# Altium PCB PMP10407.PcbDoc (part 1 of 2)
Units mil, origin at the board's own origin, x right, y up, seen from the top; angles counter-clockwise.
Board outline 4400 x 1900 mil, 4 copper layers (Top Layer, Signal Layer 1, Signal Layer 2, Bottom Layer), stack 60.6 mil thick; 66 components, 38 nets, 182 pads, 41 vias.
Unrouted connection lines stored in the file: 1.
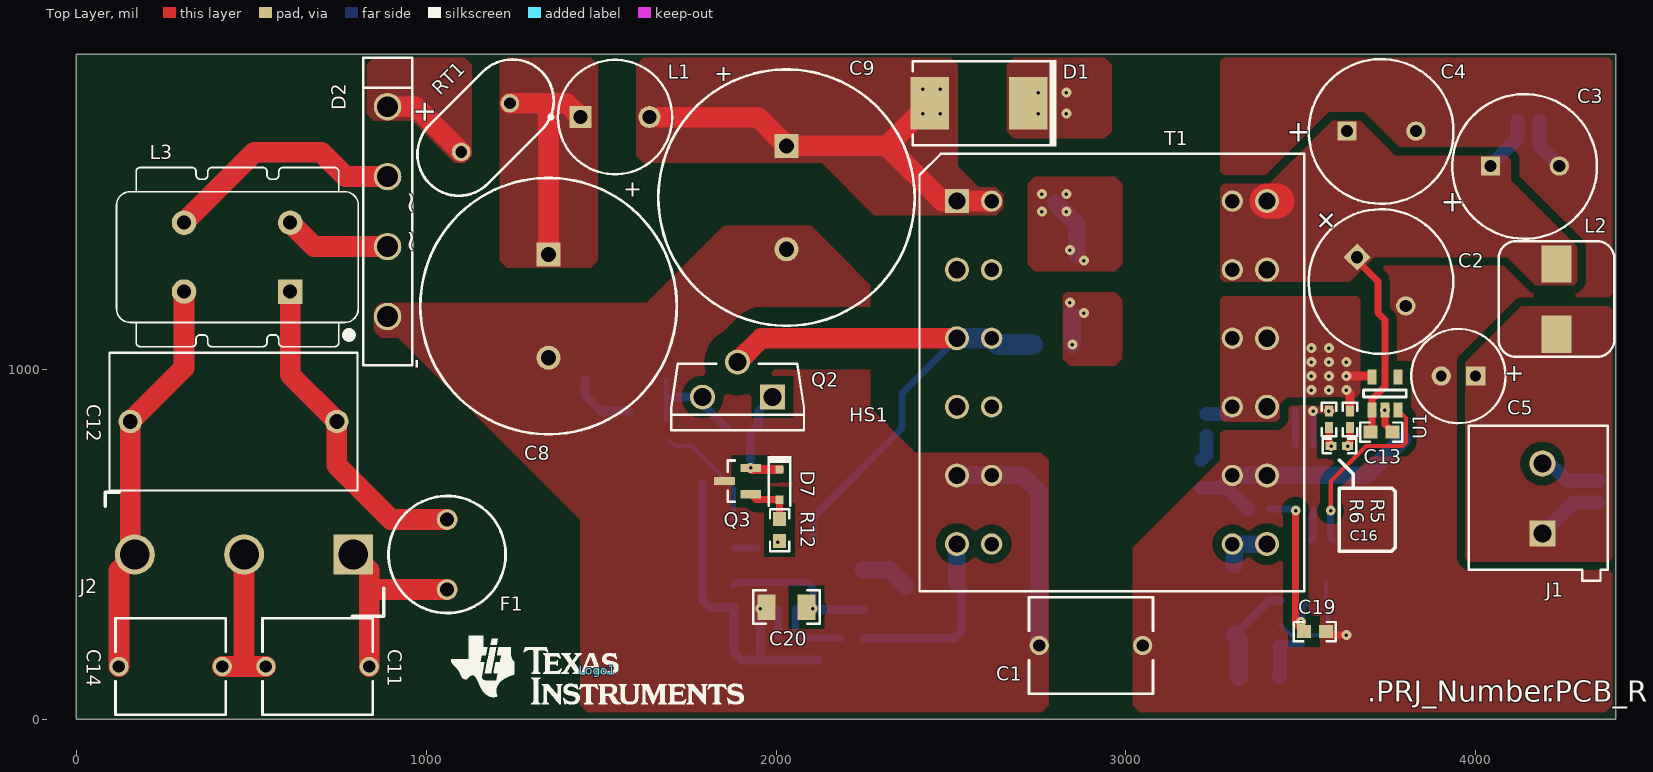
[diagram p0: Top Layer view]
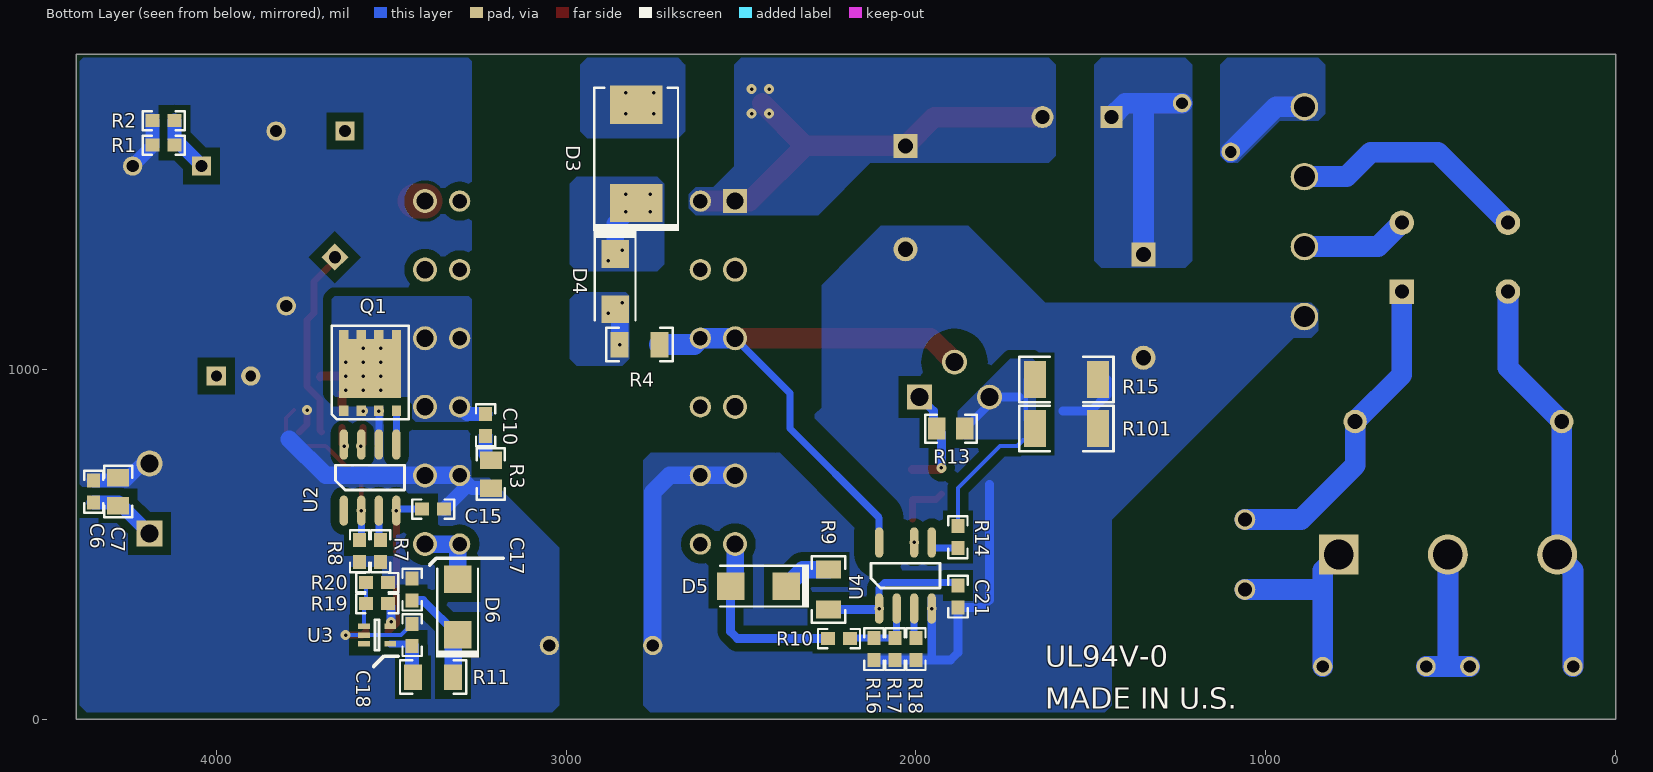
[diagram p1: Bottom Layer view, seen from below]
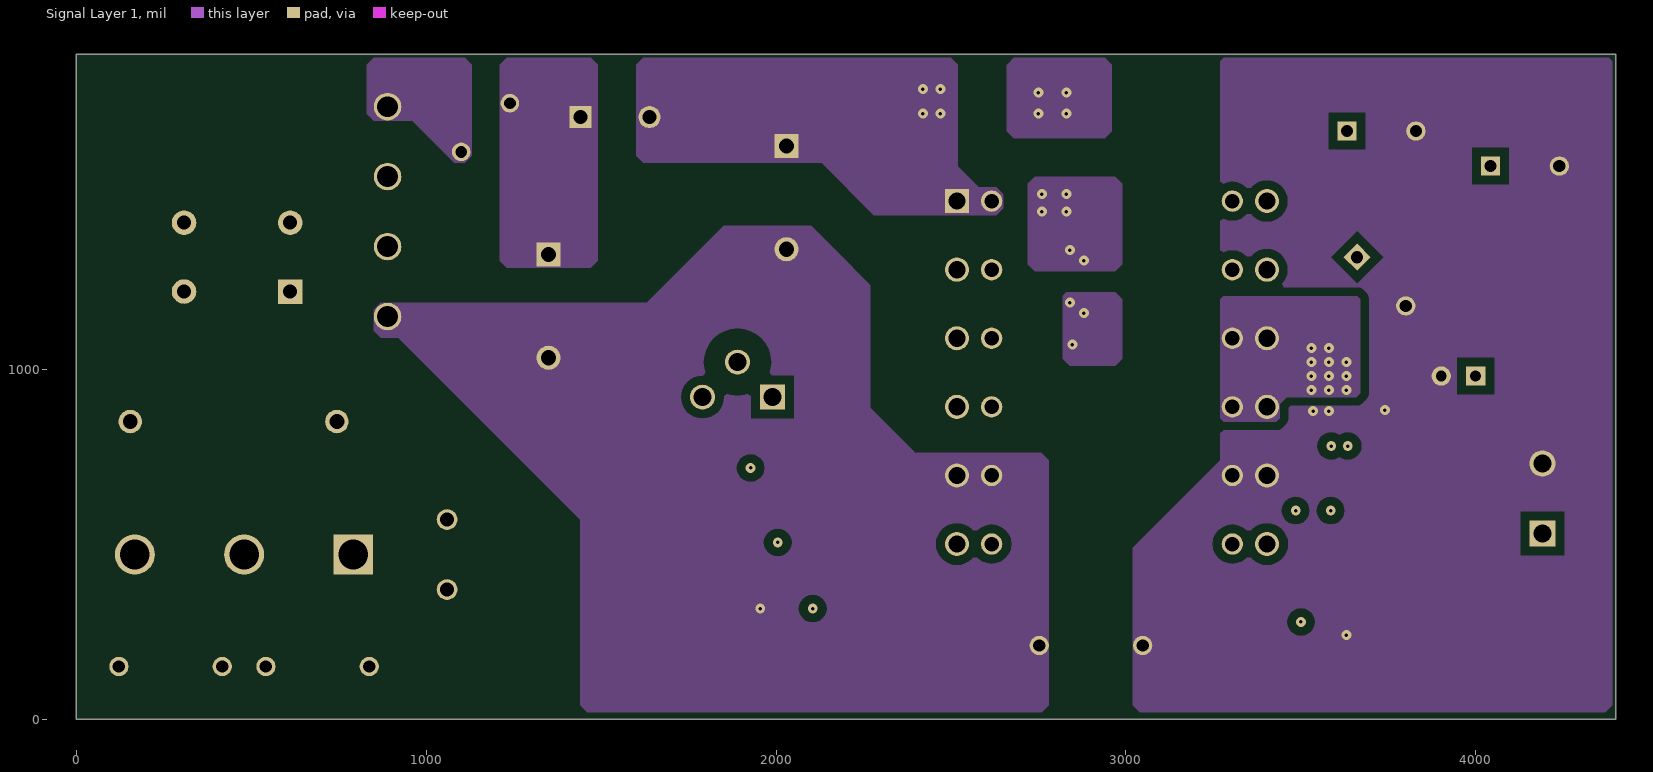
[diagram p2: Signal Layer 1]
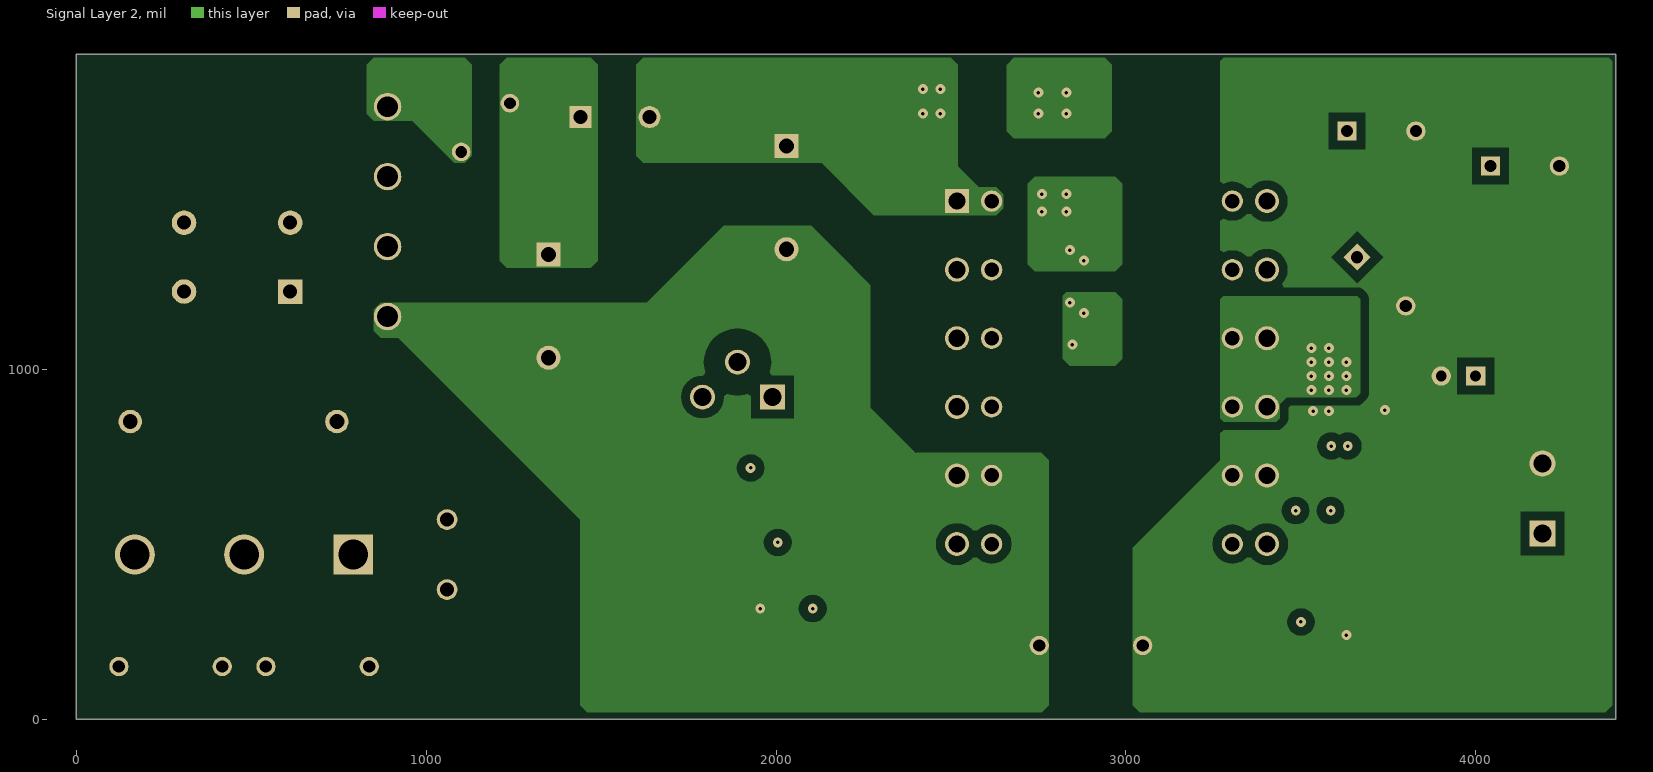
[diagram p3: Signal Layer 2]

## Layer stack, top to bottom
Top Solder: solder mask 0.4, Solder Resist, Dk 3.5
Top Layer: signal copper 1.4
Dielectric1: core 10, FR-4, Dk 4.8
Signal Layer 1: signal copper 1.4
Dielectric 3: prepreg 35, FR-4, Dk 4.2
Signal Layer 2: signal copper 1.4
Dielectric 2: core 10, FR-4, Dk 4.2
Bottom Layer: signal copper 1.4
Bottom Solder: solder mask 0.4, Solder Resist, Dk 3.5

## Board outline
0,0 4400,0 4400,1900 0,1900

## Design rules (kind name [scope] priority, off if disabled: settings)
AcuteAngle [All] p1: minimum=4.50000000000000E+0001 checktracksonly=FALSE
AssemblyTestPointUsage [All] p1: valid=2
Clearance Clearance_1 [InNetClass('HV_Pri') vs InNet('GND')] p1: gap=60
Clearance Clearance_BoardEdge_MountingHoles [OnCopper and InComponentClass('Mounting Holes') vs IsKeepOut] p2: gap=40
Clearance Clearance_BoardEdge_Poly [OnCopper and InPoly vs IsKeepOut] p3: gap=25
Clearance Clearance_BoardEdge [OnCopper and Not InComponentClass('Logo') and not InComponentClass('FiducialMark') and not InRegion(1000,500,4000,800) and Not IsKeepout vs IsKeepOut] p4: gap=75
Clearance Clearance_Poly [InPolygon] p5: gap=25
Clearance [All] p6: gap=9.5
ComponentClearance ComponentClearance_Logo [InComponentClass(Logo)] p1: gap=50 collisioncheckmode=3 verticalgap=10 showdistances=FALSE
ComponentClearance ComponentClearance_ScrewToNut [(HasFootprint('NY PMS 440 0025 PH')) vs (HasFootprint('Keystone_1902C'))] p2: gap=5 collisioncheckmode=3 verticalgap=10 showdistances=FALSE
ComponentClearance ComponentClearance_MountingHoles [InComponentClass('Mounting Holes')] p3: gap=10 collisioncheckmode=3 verticalgap=100000 showdistances=FALSE
ComponentClearance ComponentClearance_SmallPassives [HasFootprint('0201*') or HasFootprint('0402*') or HasFootprint('0508') or HasFootprint('0603*') or HasFootprint('0612') or HasFootprint('0805*') or HasFootprint('0815*') or HasFootprint('0830*') or HasFootprint('1206*') or HasFootprint('1210*') or HasFootprint('1808*') or HasFootprint('1812*') or HasFootprint('1825*') or HasFootprint('2010*') or HasFootprint('2220*') or HasFootprint('2225*') or HasFootprint('2512*') or HasFootprint('2728*') or HasFootprint('3518*') vs HasFootprint('0201*') or HasFootprint('0402*') or HasFootprint('0508') or HasFootprint('0603*') or HasFootprint('0612') or HasFootprint('0805*') or HasFootprint('0815*') or HasFootprint('0830*') or HasFootprint('1206*') or HasFootprint('1210*') or HasFootprint('1808*') or HasFootprint('1812*') or HasFootprint('1825*') or HasFootprint('2010*') or HasFootprint('2220*') or HasFootprint('2225*') or HasFootprint('2512*') or HasFootprint('2728*') or HasFootprint('3518*')] p4: gap=20 collisioncheckmode=3 verticalgap=9.5 showdistances=FALSE
ComponentClearance ComponentClearance_THtoSMT [IsThruComponent vs IsSMTComponent] p5: gap=9.5 collisioncheckmode=3 verticalgap=9.5 showdistances=FALSE
ComponentClearance ComponentClearance_THtoTH [IsThruComponent vs IsThruComponent] p6: gap=9.5 collisioncheckmode=3 verticalgap=9.5 showdistances=FALSE
ComponentClearance [All] p7: gap=9.5 collisioncheckmode=3 verticalgap=9.5 showdistances=FALSE
DiffPairsRouting [All] p1: maxlimit=100 minlimit=10 mostfreqgap=10 toplayer_minwidth=15 toplayer_maxwidth=15 toplayer_prefwidth=15 midlayer1_minwidth=15 midlayer1_maxwidth=15 midlayer1_prefwidth=15 midlayer2_minwidth=15 midlayer2_maxwidth=15 midlayer2_prefwidth=15 bottomlayer_minwidth=15 bottomlayer_maxwidth=15 bottomlayer_prefwidth=15 maxuncoupledlength=1000
FabricationTestPointUsage TestPointUsage [All] p1: valid=2 allowmultiple=FALSE
FabricationTestpoint Testpoint [All] p1: side=3 testpointundercomponent=TRUE minsize=40 maxsize=100 preferedsize=60 minholesize=0 maxholesize=40 preferedholesize=32 testpointgrid=1 allowsidetop=TRUE allowsidebottom=TRUE usegrid=TRUE gridtolerance=0.01
FanoutControl Fanout_LCC [IsLCC] p1: bgadir=Out bgaviamode=Centered fanoutstyle=Auto fanoutdirection=Alternating viagrid=1 // Fanout_LCC (Default Rule)
FanoutControl Fanout_BGA [IsBGA] p2: bgadir=Out bgaviamode=Centered fanoutstyle=Auto fanoutdirection=Alternating viagrid=1 // Fanout_BGA (Default Rule)
FanoutControl Fanout_Default [All] p4: bgadir=Out bgaviamode=Centered fanoutstyle=Auto fanoutdirection=Alternating viagrid=1 // Fanout_Default (Default Rule)
FanoutControl Fanout_Small [(CompPinCount < 5)] p5: bgadir=Out bgaviamode=Centered fanoutstyle=Auto fanoutdirection=OutThenIn viagrid=1 // Fanout_Small (Default Rule)
Height [All] p1: minheight=0 maxheight=8000 prefheight=3000
HoleSize [All] p1: absolutevalues=TRUE maxlimit=251 minlimit=8 maxpercent=80.000 minpercent=20.000
HoleToHoleClearance [All] p1: gap=8 allowstackedmicrovias=TRUE
MinimumAnnularRing [All] p1: minimumring=6
MinimumSolderMaskSliver MinimumSolderMaskSliver_Logo [InComponentClass('Logo') vs InComponentClass('Logo')] p1: minsoldermaskwidth=0.7
MinimumSolderMaskSliver [All] p2: minsoldermaskwidth=3.5
PlaneConnect [All] p1: planeconnectstyle=Relief reliefexpansion=10 reliefentries=4 reliefconductorwidth=10 reliefairgap=10
PolygonConnect PolygonConnect_14 [All vs IsNamedPolygon('NetC2_1') Or  IsNamedPolygon('D2_1') Or  IsNamedPolygon('D3_1') Or  IsNamedPolygon('D1_1') Or  IsNamedPolygon('C8_1') Or  IsNamedPolygon('C10_2') Or  IsNamedPolygon('GND') Or  IsNamedPolygon('C10_2') Or  IsNamedPolygon('C9_1') Or  IsNamedPolygon('C10_2') Or  IsNamedPolygon('Q2_3') Or  IsNamedPolygon('C10_2') Or  IsNamedPolygon('GND') Or  IsNamedPolygon('D2_1') Or  IsNamedPolygon('C9_1') Or  IsNamedPolygon('D1_1') Or  IsNamedPolygon('D4_2') Or  IsNamedPolygon('C8_1')] p1: connectstyle=Direct reliefconductorwidth=10 reliefentries=4 polygonreliefangle="90 Angle" airgapwidth=10
PolygonConnect PolygonConnect_13 [All vs IsNamedPolygon('GND') Or  IsNamedPolygon('GND2') Or  IsNamedPolygon('GND') Or  IsNamedPolygon('GND2') Or  IsNamedPolygon('Q2_3') Or  IsNamedPolygon('D1_1') Or  IsNamedPolygon('D1_1') Or  IsNamedPolygon('C2_1') Or  IsNamedPolygon('C9_1') Or  IsNamedPolygon('C2_1') Or  IsNamedPolygon('C8_1') Or  IsNamedPolygon('D3_1') Or  IsNamedPolygon('C8_1') Or  IsNamedPolygon('D2_1') Or  IsNamedPolygon('C5_1') Or  IsNamedPolygon('C9_1') Or  IsNamedPolygon('D4_2') Or  IsNamedPolygon('C5_1') Or  IsNamedPolygon('C10_2') Or  IsNamedPolygon('C10_2') Or  IsNamedPolygon('D2_1')] p2: connectstyle=Direct reliefconductorwidth=10 reliefentries=4 polygonreliefangle="90 Angle" airgapwidth=10
PolygonConnect PolygonConnect_12 [All vs IsNamedPolygon('GND') Or  IsNamedPolygon('GND') Or  IsNamedPolygon('C5_1') Or  IsNamedPolygon('C8_1') Or  IsNamedPolygon('D2_1') Or  IsNamedPolygon('Q2_3') Or  IsNamedPolygon('C9_1') Or  IsNamedPolygon('C10_2') Or  IsNamedPolygon('D3_1') Or  IsNamedPolygon('C9_1') Or  IsNamedPolygon('D4_2') Or  IsNamedPolygon('C2_1') Or  IsNamedPolygon('C2_1') Or  IsNamedPolygon('C10_2') Or  IsNamedPolygon('D2_1') Or  IsNamedPolygon('D1_1') Or  IsNamedPolygon('C8_1') Or  IsNamedPolygon('D1_1') Or  IsNamedPolygon('C5_1')] p3: connectstyle=Direct reliefconductorwidth=10 reliefentries=4 polygonreliefangle="90 Angle" airgapwidth=10
PolygonConnect PolygonConnect_11 [All vs IsNamedPolygon('C10_2') Or  IsNamedPolygon('C2_1') Or  IsNamedPolygon('C5_1') Or  IsNamedPolygon('D1_1') Or  IsNamedPolygon('C9_1') Or  IsNamedPolygon('C8_1') Or  IsNamedPolygon('C9_1') Or  IsNamedPolygon('C10_2') Or  IsNamedPolygon('C2_1') Or  IsNamedPolygon('D1_1') Or  IsNamedPolygon('C8_1') Or  IsNamedPolygon('D4_2') Or  IsNamedPolygon('D2_1') Or  IsNamedPolygon('C5_1') Or  IsNamedPolygon('D3_1') Or  IsNamedPolygon('D2_1')] p4: connectstyle=Direct reliefconductorwidth=10 reliefentries=4 polygonreliefangle="90 Angle" airgapwidth=10
PolygonConnect PolygonConnect_10 [All vs IsNamedPolygon('C8_1') Or  IsNamedPolygon('C2_1') Or  IsNamedPolygon('D1_1') Or  IsNamedPolygon('D1_1') Or  IsNamedPolygon('D4_2') Or  IsNamedPolygon('D2_1') Or  IsNamedPolygon('D3_1') Or  IsNamedPolygon('C9_1') Or  IsNamedPolygon('D2_1') Or  IsNamedPolygon('C9_1') Or  IsNamedPolygon('C8_1')] p5: connectstyle=Direct reliefconductorwidth=10 reliefentries=4 polygonreliefangle="90 Angle" airgapwidth=10
PolygonConnect PolygonConnect_9 [All vs IsNamedPolygon('C4_1') Or  IsNamedPolygon('C2_1_T') Or  IsNamedPolygon('C2_1_B') Or  IsNamedPolygon('D4_1') Or  IsNamedPolygon('GND2') Or  IsNamedPolygon('GND') Or  IsNamedPolygon('D4_1') Or  IsNamedPolygon('D2_1') Or  IsNamedPolygon('Q1_3_B') Or  IsNamedPolygon('C6_1') Or  IsNamedPolygon('GND2_T') Or  IsNamedPolygon('D2_1') Or  IsNamedPolygon('GND') Or  IsNamedPolygon('GND2') Or  IsNamedPolygon('GND2')] p6: connectstyle=Direct reliefconductorwidth=10 reliefentries=4 polygonreliefangle="90 Angle" airgapwidth=10
PolygonConnect PolygonConnect_8 [All vs IsNamedPolygon('GND2') Or  IsNamedPolygon('C2_1_B') Or  IsNamedPolygon('C6_1') Or  IsNamedPolygon('GND') Or  IsNamedPolygon('D2_1') Or  IsNamedPolygon('Q1_3_B') Or  IsNamedPolygon('D4_1') Or  IsNamedPolygon('C2_1_T') Or  IsNamedPolygon('D2_1') Or  IsNamedPolygon('D4_1') Or  IsNamedPolygon('GND2_T') Or  IsNamedPolygon('GND') Or  IsNamedPolygon('C4_1')] p7: connectstyle=Direct reliefconductorwidth=10 reliefentries=4 polygonreliefangle="90 Angle" airgapwidth=10
PolygonConnect PolygonConnect_7 [All vs IsNamedPolygon('Q1_3_B') Or  IsNamedPolygon('C2_1_T') Or  IsNamedPolygon('D4_1') Or  IsNamedPolygon('C4_1') Or  IsNamedPolygon('D2_1') Or  IsNamedPolygon('GND2_T') Or  IsNamedPolygon('D2_1') Or  IsNamedPolygon('D4_1') Or  IsNamedPolygon('C2_1_B')] p8: connectstyle=Direct reliefconductorwidth=10 reliefentries=4 polygonreliefangle="90 Angle" airgapwidth=10
PolygonConnect PolygonConnect_6 [All vs IsNamedPolygon('C1_1_T') Or  IsNamedPolygon('GND_T') Or  IsNamedPolygon('C5_1_B') Or  IsNamedPolygon('D4_1_B') Or  IsNamedPolygon('D2_1_B') Or  IsNamedPolygon('D4_1_T') Or  IsNamedPolygon('C3_2_T') Or  IsNamedPolygon('GND') Or  IsNamedPolygon('C2_1_T') Or  IsNamedPolygon('Q1_3_B') Or  IsNamedPolygon('C3_2_B') Or  IsNamedPolygon('C5_1_T') Or  IsNamedPolygon('C5_1_B') Or  IsNamedPolygon('D2_1_T') Or  IsNamedPolygon('C2_1_B')] p9: connectstyle=Direct reliefconductorwidth=10 reliefentries=4 polygonreliefangle="90 Angle" airgapwidth=10
PolygonConnect PolygonConnect_5 [All vs IsNamedPolygon('C1_1_T') Or  IsNamedPolygon('D2_1_T') Or  IsNamedPolygon('C2_1_T') Or  IsNamedPolygon('D4_1_B') Or  IsNamedPolygon('D2_1_B') Or  IsNamedPolygon('D4_1_T') Or  IsNamedPolygon('Q1_3_B') Or  IsNamedPolygon('C2_1_B')] p10: connectstyle=Direct reliefconductorwidth=10 reliefentries=4 polygonreliefangle="90 Angle" airgapwidth=10
PolygonConnect PolygonConnect_4 [All vs IsNamedPolygon('D1_2_B') Or  IsNamedPolygon('D1_3_T') Or  IsNamedPolygon('D1_3_B') Or  IsNamedPolygon('C2_1_T') Or  IsNamedPolygon('C5_1_B') Or  IsNamedPolygon('C5_1_T') Or  IsNamedPolygon('C7_1_B') Or  IsNamedPolygon('C7_1_T') Or  IsNamedPolygon('D1_2_T') Or  IsNamedPolygon('VCS_T') Or  IsNamedPolygon('L4_9_T') Or  IsNamedPolygon('C12_1_T') Or  IsNamedPolygon('D4_1_T') Or  IsNamedPolygon('C9_1_T') Or  IsNamedPolygon('Q7_4_B') Or  IsNamedPolygon('R23_2_B') Or  IsNamedPolygon('VREC_T') Or  IsNamedPolygon('C9_1_B') Or  IsNamedPolygon('D6_1_T') Or  IsNamedPolygon('VREC_B') Or  IsNamedPolygon('L4_3_B') Or  IsNamedPolygon('D4_1_B') Or  IsNamedPolygon('C9_1_T')] p11: connectstyle=Direct reliefconductorwidth=10 reliefentries=4 polygonreliefangle="90 Angle" airgapwidth=10
PolygonConnect PolygonConnect_3 [All vs IsNamedPolygon('VCS_T') Or  IsNamedPolygon('VREC_B') Or  IsNamedPolygon('C5_1_T') Or  IsNamedPolygon('D1_2_T') Or  IsNamedPolygon('L4_9_T') Or  IsNamedPolygon('Q7_4_B') Or  IsNamedPolygon('D4_1_B') Or  IsNamedPolygon('D1_3_B') Or  IsNamedPolygon('R23_2_B') Or  IsNamedPolygon('VREC_T') Or  IsNamedPolygon('C7_1_T') Or  IsNamedPolygon('C7_1_B') Or  IsNamedPolygon('C2_1_T') Or  IsNamedPolygon('D1_3_T') Or  IsNamedPolygon('C5_1_B') Or  IsNamedPolygon('D4_1_T') Or  IsNamedPolygon('D1_2_B') Or  IsNamedPolygon('L4_3_B')] p12: connectstyle=Direct reliefconductorwidth=10 reliefentries=4 polygonreliefangle="90 Angle" airgapwidth=10
PolygonConnect PolygonConnect_2 [All vs IsNamedPolygon('GND_T') Or  IsNamedPolygon('Vrec_T') Or  IsNamedPolygon('Vout1_T') Or  IsNamedPolygon('C2_1_B') Or  IsNamedPolygon('D1_3_T') Or  IsNamedPolygon('Vout1_B') Or  IsNamedPolygon('C2_1_T') Or  IsNamedPolygon('D1_2_T') Or  IsNamedPolygon('Vout_T') Or  IsNamedPolygon('Q1_5_B') Or  IsNamedPolygon('Vout_B') Or  IsNamedPolygon('Vrec_B') Or  IsNamedPolygon('D1_2_B') Or  IsNamedPolygon('Q9_5_B') Or  IsNamedPolygon('Q9_5_T') Or  IsNamedPolygon('Q1_5_T') Or  IsNamedPolygon('GND2_T') Or  IsNamedPolygon('GND_B') Or  IsNamedPolygon('GND2_B') Or  IsNamedPolygon('D1_3_B') Or  IsNamedPolygon('C3_2_T') Or  IsNamedPolygon('C7_1_T') Or  IsNamedPolygon('C3_2_B') Or  IsNamedPolygon('C7_1_V')] p13: connectstyle=Direct reliefconductorwidth=10 reliefentries=4 polygonreliefangle="90 Angle" airgapwidth=10
PolygonConnect PolygonConnect_1 [All vs IsNamedPolygon('C7_1_V') Or  IsNamedPolygon('D1_2_T') Or  IsNamedPolygon('Vrec_B') Or  IsNamedPolygon('C2_1_B') Or  IsNamedPolygon('D1_2_B') Or  IsNamedPolygon('C7_1_T') Or  IsNamedPolygon('C3_2_B') Or  IsNamedPolygon('Vout_B') Or  IsNamedPolygon('Vout1_B') Or  IsNamedPolygon('C3_2_T') Or  IsNamedPolygon('Vrec_T') Or  IsNamedPolygon('Q1_5_T') Or  IsNamedPolygon('Q9_5_B') Or  IsNamedPolygon('C2_1_T') Or  IsNamedPolygon('Q1_5_B') Or  IsNamedPolygon('Vout_T') Or  IsNamedPolygon('D1_3_B') Or  IsNamedPolygon('Vout1_T') Or  IsNamedPolygon('Q9_5_T') Or  IsNamedPolygon('D1_3_T')] p14: connectstyle=Direct reliefconductorwidth=10 reliefentries=4 polygonreliefangle="90 Angle" airgapwidth=10
PolygonConnect [All] p15: connectstyle=Relief reliefconductorwidth=10 reliefentries=4 polygonreliefangle="90 Angle" airgapwidth=10
RoutingVias [All] p1: holewidth=16 width=34 viastyle="Through Hole" minholewidth=8 minwidth=26 maxholewidth=200 maxwidth=250
SMDToCorner [All] p1: distance=30000
SilkToSilkClearance [All] p1: silktosilkclearance=5
SilkToSolderMaskClearance SilkscreenOverComponentPads [IsPad] p1: minsilkscreentomaskgap=5 clearancetoexposedcopper=TRUE
SolderMaskExpansion [All] p1: expansion=3
UnpouredPolygon [All] p1: allowunpoured=FALSE
Width [All] p1: maxlimit=100 minlimit=6 preferedwidth=10 checkconnectedcopper=TRUE
13 further rules are at their usual default settings.

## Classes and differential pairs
component class Logo: Logo1
net class HV_Pri: NetC9_1 NetC12_1 NetC12_2 NetD1_1 NetD2_1 NetD2_3 NetD3_1 NetQ2_2

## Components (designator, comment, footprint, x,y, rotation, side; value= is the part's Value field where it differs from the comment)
C1 "DE6E3KJ222MN3A" E_900x700x900 2900,210 r180 top
C2 "PLE0J681MDO1" CAPPRD500W60D1000H1250 3730,1250 r315 top
C3 "PLE0J681MDO1" CAPPRD500W60D1000H1250 4140,1580 r0 top
C4 "PLE0J681MDO1" CAPPRD500W60D1000H1250 3730,1680 r0 top
C5 "6.3YXJ470M6.3X11" SEPC_C55 3950,980 r180 top
C6 "C0603C105K4PACTU" 0603 4350,650 r90 bottom
C7 "08053C104KAT2A" 0805_HV 4280,650 r90 bottom
C8 "EKXG401ELL470MM20S" EE_1800x2000 1350,1180 r270 top
C9 "400BXW68MEFC18X20" EE_1800x2000 2030,1490 r270 top
C10 "C1608C0G2A101J" 0603 3230,840 r90 bottom
C11 "DE6B3KJ221KN3A" B_800x700x800 690,150 r180 top
C12 "ECQ-U2A334ML" CAPRR1500W80L1750T950H1750 450,850 r180 top
C13 "C0603C105K4PACTU" 0603 3730,820 r0 top
C14 "DE6B3KJ221KN3A" B_800x700x800 270,150 r180 top
C15 "C0603C105K4PACTU" 0603 3380,600 r180 bottom
C16 "GRM1555C1E470JA01D" 0402 3610,780 r180 top
C17 "0603ZD475KAT2A" 0603 3440,370 r90 bottom
C18 "C0603C105K4PACTU" 0603 3440,240 r90 bottom
C19 "C0603C105K4PACTU" 0603 3540,250 r0 top
C20 "GRM316R61E225KA12D" 1206 2030,320 r180 top
C21 "06035C104KAT2A" 0603 1880,350 r270 bottom
D1 "SMCJ85A" SMC 2580,1760 r180 top
D2 "GBU4K-E3/45" GBU 890,1450 r270 top
D3 "SMCJ85A" SMC 2800,1615 r90 bottom
D4 "US1M-13-F" SMA 2860,1250 r270 bottom
D5 "ES1D-13-F" SMA 2450,380 r0 bottom
D6 "CDBA140-G" SMA 3310,320 r90 bottom
D7 "BAT54HT1G" sod-323 2010,670 r270 top
F1 "FUSE FAST 250VAC 2A RADIAL" FUSE_372 1060,470 r270 top
HS1 "576012B00000G" Aavid_530614B00000G 1890,810 r270 top
J1 "1715721" PhoenixContact_1715721 4190,630 r90 top
J2 "1-1318301-3" TE_1-1318301-3 480,470 r180 top
L1 "744772101" IND_WE-TI_8095 1540,1720 r0 top
L2 "744314110" WE-HC3 4230,1200 r270 top
L3 "744822110" IND_WE-CMB-S 460,1320 r90 top
Logo1 "Texas Instruments" TI_Stacked_Overlay_Small 1490,140 r0 top
Q1 "CSD18501Q5A" TRANS_NexFET_Q5A 3560,990 r90 bottom
Q2 "IPP65R380E6" TO-220AB_100mil 1990,920 r180 top
Q3 "MMBT2907A" SOT-23 1890,680 r180 top
R1 "CRCW0603100KJNEA" 0603 4150,1640 r180 bottom
R2 "CRCW0603100KJNEA" 0603 4150,1710 r180 bottom
R3 "CRCW08050000Z0EA" 0805_HV 3215,700 r270 bottom
R4 "CRCW120620R0FKEA" 1206 2790,1070 r180 bottom
R5 "CRCW04020000Z0ED" 0402 3640,856.14 r90 top
R6 "CRCW0402100RFKED" 0402 3580,856.14 r90 top
R7 "CRCW060349K9FKEA" 0603 3530,480 r90 bottom
R8 "CRCW0603221KFKEA" 0603 3590,480 r90 bottom
R9 "CRCW1206100RJNEA" 1206 2250,370 r90 bottom
R10 "CRCW060397K6FKEA" 0603 2220,230 r0 bottom
R11 "CRCW12061R00JNEA" 1206 3380,120 r0 bottom
R12 "CRCW060310R0JNEA" 0603 2010,540 r270 top
R13 "CRCW0805100KJNEA" 0805_HV 1900,830 r0 bottom
R14 "CRCW0603590RFKEA" 0603 1880,520 r90 bottom
R15 "ERJ-12ZQJR47U" 2010 1570,970 r0 bottom
R16 "CRCW060347K5FKEA" 0603 2120,200 r90 bottom
R17 "CRCW060347K5FKEA" 0603 2060,200 r90 bottom
R18 "CRCW060336K5FKEA" 0603 2000,200 r90 bottom
R19 "CRCW06033M16FKEA" 0603 3540,330 r0 bottom
R20 "CRCW06031M00JNEA" 0603 3540,390 r0 bottom
R101 "ERJ-12ZQJR47U" 2010 1570,830 r0 bottom
RT1 "B57236S0100M000" THERM_B57236S0 1170,1690 r225 top
T1 "RLTI-1123" RENCO_RLTI-1123 2960,990 r0 top
U1 "UCC24650DBV" DBV0005A_N 3740,930 r90 top
U2 "UCC24610D" D0008A_N 3560,690 r90 bottom
U3 "TPS71550DCK" DCK0005A_N 3540,240 r180 bottom
U4 "UCC28730D" D0007A_N 2030,410 r90 bottom

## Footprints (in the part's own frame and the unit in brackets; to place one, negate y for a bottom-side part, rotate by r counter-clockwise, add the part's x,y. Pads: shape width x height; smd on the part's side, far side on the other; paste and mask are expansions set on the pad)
0402 [mm] "0402 from SM-752 data"
  rect 0.8x0.6 smd: 1(-0.6,0) 2(0.6,0)
  silkscreen extent -1.22,-0.52 1.22,0.52, body extent -0.55,-0.3 0.55,0.3, height 0.6
0603 [mm] "0603 from SM-752 data"
  rect 1x0.95 smd: 1(-0.8,0) 2(0.8,0)
  silkscreen extent -1.52,-0.69 1.52,0.69, body extent -0.87,-0.47 0.87,0.47, height 0.85
0805_HV [mil] "0805 with 30mil clearance between pads"
  rect 50x63 smd: 1(-40,0) 2(40,0)
  silkscreen extent -74,-40 74,40, body extent -43,-29 43,29, height 43
1206 [mm] "1206 from SM-752 data"
  rect 1.3x1.85 smd: 1(-1.45,0) 2(1.45,0)
  silkscreen extent -2.4,-1.21 2.4,1.21, body extent -1.7,-0.9 1.7,0.9, height 1.35
2010 [mm] "Chip Capacitor, Body 5.08x2.54mm, IPC Medium Density"
  rect 1.6x2.7 smd: 1(-2.3,0) 2(2.3,0)
  silkscreen extent -3.42,-1.65 3.42,1.65, body extent -2.73,-1.45 2.73,1.45, height 1.66
Aavid_530614B00000G [mil] "Aavid"
  round 1 on Mech3: 0(0,0)
  body extent 0,-500 500,500, height 1181
B_800x700x800 [mm] "TH, 2- Leads, Body 8x7mm, Pin Spacing 7.5mm"
  round 1.4 hole 0.9: 1(-3.75,0) 2(3.75,0)
  silkscreen extent -4,-3.5 4,3.5, body extent -4.05,-3.5 4.05,3.5, height 10.97
CAPPRD500W60D1000H1250 [mm] "Capacitor, Electrolytic, Radial; Body 10 x 12.5 mm (Dia.xH typ); Pin Spacing 5 mm (typ)"
  rect 1.4x1.4 hole 0.889: 1(-2.5,0)
  round 1.4 hole 0.889: 2(2.5,0)
  silkscreen extent -5.27,-5.27 5.22,5.22, body extent -5,-4.99 5,4.99, height 14.12
CAPRR1500W80L1750T950H1750 [mm] "PANASONIC"
  round 1.7 hole 1.069: 1(-7.5,0) 2(7.5,0)
  silkscreen extent -9,-5 9,5, body extent -9,-5 9,5, height 18
D0007A_N [mm] "SOIC, 7-Leads, Body 4.9x3.9mm, Pitch 1.27mm, IPC Medium Density"
  oval 2.2x0.6 smd: 1(-2.4,1.905) 2(-2.4,0.635) 3(-2.4,-0.635) 4(-2.4,-1.905) 5(2.4,-1.905) 6(2.4,-0.635) 8(2.4,1.905)
  silkscreen extent -0.9,-2.5 0.9,2.5, body extent -3,-2.5 3,2.5, height 1.54
D0008A_N [mm] "SOIC, 8-Leads, Body 4.9x3.9mm, Pitch 1.27mm, IPC Medium Density"
  oval 2.2x0.6 smd: 1(-2.4,1.905) 2(-2.4,0.635) 3(-2.4,-0.635) 4(-2.4,-1.905) 5(2.4,-1.905) 6(2.4,-0.635) 7(2.4,0.635) 8(2.4,1.905)
  silkscreen extent -0.9,-2.5 0.9,2.5, body extent -3,-2.45 3,2.45, height 1.63
DBV0005A_N [mm] "SOT23, 5-Leads, Body 2.9x1.6mm, Pitch 0.95mm, Lead Span 2.8mm, IPC Medium Density"
  rect 1.1x0.65 smd: 1(-1.2,0.95) 2(-1.2,0) 3(-1.2,-0.95) 4(1.2,-0.95) 5(1.2,0.95)
  silkscreen extent -0.25,-1.55 0.25,1.55, body extent -1.42,-1.46 1.42,1.46, height 1.08
DCK0005A_N [mm] "SOT353, 5-Leads, Body 2x1.3mm, Pitch 0.65mm, Lead Span 2.1mm, IPC Medium Density"
  rect 0.85x0.4 smd: 1(-0.95,0.65) 2(-0.95,0) 3(-0.95,-0.65) 4(0.95,-0.65) 5(0.95,0.65)
  silkscreen extent -0.15,-1.1 0.15,1.1, body extent -1.14,-1 1.14,1, height 0.94
E_900x700x900 [mm] "TH, 2- Leads, Body 9x7mm, Pin Spacing 7.5mm"
  round 1.4 hole 0.9: 1(-3.75,0) 2(3.75,0)
  silkscreen extent -4.5,-3.5 4.5,3.5, body extent -4.49,-3.5 4.49,3.5, height 11.96
EE_1800x2000 [mm] "PANASONIC"
  rect 1.75x1.75 hole 1.1: 1(-3.75,0)
  round 1.75 hole 1.1: 2(3.75,0)
  silkscreen extent -9.3,-9.3 9.3,9.3, body extent -9.18,-9.23 9.22,9.24, height 22.01
FUSE_372 [mm] "LITTELFUSE"
  round 1.5 hole 1: 1(-2.54,0) 2(2.54,0)
  silkscreen extent -4.25,-4.25 4.25,4.25, body extent -4.26,-4.26 4.26,4.26, height 8
GBU [mm] "Comchip / Diodes Inc diode bridge"
  round 2 hole 1.5: 1(-7.62,0) 2(-2.54,0) 3(2.54,0) 4(7.62,0)
  silkscreen extent -11.15,-1.78 11.15,1.78, body extent -11.15,-1.76 11.15,1.8, height 21.55
IND_WE-CMB-S [mil] "Inductor, WE CMB Series Size S"
  rect 70x70 hole 40: 1(-98.43,-151.57)
  round 70 hole 40: 2(98.43,-151.57) 3(98.43,151.57) 4(-98.43,151.57)
  silkscreen extent -256,-346 256,344, body extent -256,-290 256,288, height 788
IND_WE-TI_8095 [mm] "Wurth WE-TI 8095"
  rect 1.6x1.6 hole 1: 1(-2.5,0)
  round 1.6 hole 1: 2(2.5,0)
  silkscreen extent -4.79,-4.15 4.15,4.15, body extent -4.12,-4.14 4.15,4.14, height 10
PhoenixContact_1715721 [mm] "Phoenix Contact 1715721 used on LM3445 design from Longmont"
  rect 1.905x1.905 hole 1.3: 1(-2.54,0)
  round 1.9 hole 1.3: 2(2.54,0)
  silkscreen extent -5.97,-4.75 5.28,5.36, body extent -5.82,-4.6 5.08,5.2, height 14.2
RENCO_RLTI-1123 [mm] "TH, 24-Leads, Body 1250x1100mil"
  rect 1.75x1.75 hole 1.25: 1(-11.252,12.446)
  round 1.75 hole 1.25: 2(-11.252,7.468) 3(-11.252,2.489) 4(-11.252,-2.489) 5(-11.252,-7.468) 6(-11.252,-12.446) 19(11.252,-12.446) 20(11.252,-7.468) 21(11.252,-2.489) 22(11.252,2.489) 23(11.252,7.468) 24(11.252,12.446)
  round 1.55 hole 1.05: 7(-8.738,-12.446) 8(-8.738,-7.468) 9(-8.738,-2.489) 10(-8.738,2.489) 11(-8.738,7.468) 12(-8.738,12.446) 13(8.738,12.446) 14(8.738,7.468) 15(8.738,2.489) 16(8.738,-2.489) 17(8.738,-7.468) 18(8.738,-12.446)
  silkscreen extent -13.97,-15.88 13.97,15.88, body extent -13.98,-15.88 13.98,15.88, height 31.24
SEPC_C55 [mm] "PANASONIC"
  rect 1.4x1.4 hole 0.787: 1(-1.25,0)
  round 1.4 hole 0.787: 2(1.25,0)
  silkscreen extent -3.42,-3.42 3.42,3.42, body extent -3.41,-3.41 3.41,3.41, height 5.52
SMA [mm] "Molded Diode, 2-Leads, Body 4.3x2.6mm, IPC Medium Density, based on OnSemi component dimensions and land pattern"
  rect 2x2 smd: 1(-2,0) 2(2,0)
  silkscreen extent -3.66,-1.57 2.79,1.57, body extent -2.6,-1.3 2.6,1.3, height 2.42
SMC [mil] "Molded Diode, 2-Leads, Body 6.9x5.8mm, IPC Medium Density, based on OnSemi component dimensions and land patterns"
  rect 110x150 smd: 1(-140.49,0) 2(140.49,0)
  silkscreen extent -221,-124 189,123, body extent -156,-116 156,116, height 91
sod-323 [mm] "NXP recommended land pattern"
  rect 0.6x0.6 smd paste-0.05: 1(-1.1,0) 2(1.1,0)
  silkscreen extent -2.06,-0.86 1.53,0.86, body extent -1.3,-0.67 1.3,0.68, height 1.1
SOT-23 [mm] "SOT23, 3-Leads, Body 2.9x1.3mm, Pitch 0.95mm, Lead Span 2.5mm, IPC Medium Density"
  rect 1.5x0.6 smd: 1(-0.95,0.95) 2(-0.95,-0.95) 3(0.95,0)
  silkscreen extent 0.2,-1.5 0.7,1.5, body extent -1.16,-1.45 1.21,1.45, height 1
TE_1-1318301-3 [mm] "TE"
  rect 2.9x2.9 hole 2.15: 1(-7.925,0)
  round 2.9 hole 2.15: 2(0,0) 3(7.925,0)
  silkscreen extent -10.13,-4.53 10.08,4.46, body extent -9.87,-4.28 9.87,4.22, height 10.72
THERM_B57236S0 [mm] "EPCOS"
  round 1.35 hole 0.85: 1(-2.5,0) 2(2.5,0)
  silkscreen extent -5.75,-3 5.75,3, body extent -5.75,-3 5.7,3, height 15.99
TI_Stacked_Overlay_Small [mil]
  silkscreen extent -418,-98 418,98
TO-220AB_100mil [mm] "High Voltage staggered pins"
  rect 1.8x1.8 hole 1.3: 1(0,0)
  round 1.8 hole 1.3: 2(2.54,-2.54) 3(5.08,0)
  silkscreen extent -2.29,-2.41 7.36,2.43, body extent -2.28,-2.84 7.37,2.43, height 22.88
TRANS_NexFET_Q5A [mm] "TI recommended land pattern (nominal) M0139-01"
  rect 0.75x0.675 smd paste-0.1 mask+0.051: 1(-2.776,1.917) 2(-2.776,0.639) 3(-2.776,-0.639) 4(-2.776,-1.917)
  rect 0.655x0.675 smd paste-0.1 mask+0.051: 5(2.776,-1.917) 6(2.776,-0.639) 7(2.776,0.639) 8(2.776,1.917)
  rect 4.295x4.51 smd paste-2.2 mask+0.051: 9(0.301,0)
  silkscreen extent -3.4,-2.8 3.4,2.8, body extent -3.05,-2.5 3.05,2.5, height 1.11
WE-HC3 [mm] "Wurth Electronik recommended land pattern"
  rect 2.7x2.2 smd: 1(-2.55,0) 2(2.55,0)
  silkscreen extent -4.2,-4.2 4.2,4.2, body extent -3.71,-3.61 3.71,3.61, height 5

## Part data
C1: "CAP, CERM, 2200 pF, 300 V, +/- 20%, E, TH, 2- Leads, Body 9x7mm, Pin Spacing 7.5mm"
C2 C3 C4: library part UVY2G4R7MPD, "CAP ALUM 680UF 6.3V 20% RADIAL"
C5: library part 6SEPC220M, "CAP ALUM 470UF 6.3V 20% RADIAL"
C6: "CAP, CERM, 1 µF, 16 V, +/- 10%, X5R, 0603"
C7: "CAP, CERM, 0.1uF, 25V, +/-10%, X7R, 0805"
C8: library part EEU-EE2G470S, "CAP ALUM 47UF 400V 20% RADIAL"
C9: library part EEU-EE2G470S, "CAP ALUM 68UF 400V 20% RADIAL"
C10: "CAP, CERM, 100pF, 100V, +/-5%, C0G/NP0, 0603"
C11 C14: "CAP, CERM, 220 pF, 300 V, +/- 10%, B, TH, 2- Leads, Body 8x7mm, Pin Spacing 7.5mm"
C12: "CAP, Film, 0.33uF, 275V, +/-20%, TH"
C13 C15 C18 C19: "CAP, CERM, 1uF, 16V, +/-10%, X5R, 0603"
C16: "CAP, CERM, 47pF, 25V, +/-5%, C0G/NP0, 0402"
C17: "CAP, CERM, 4.7 µF, 10 V, +/- 10%, X5R, 0603"
C20: "CAP, CERM, 2.2 µF, 25 V, +/- 10%, X5R, 1206"
C21: "CAP, CERM, 0.1uF, 50V, +/-10%, X7R, 0603"
D1 D3: library part SMCJ60A, "TVS DIODE 85VWM 137VC SMC"
D2: "Diode, Switching-Bridge, 800V, 4A, TH"
D4: "Diode, Ultrafast, 1000V, 1A, SMA"
D5: "Diode, Ultrafast, 200V, 1A, SMA"
D6: library part BYS10-45-E3/TR, "DIODE SCHOTTKY 40V 1A DO214AC"
D7: "Diode, Schottky, 30V, 0.2A, SOD-323"
F1: library part 37215000001
HS1: library part 530614B00000G, "Heat Sink, TO-220, TH"
J1: "Conn Term Block, 2POS, 5.08mm, TH"
J2: "HEADER, .312 VERT 3POS"
L1: library part 744772100, "INDUCTOR 100UH .9A 8095 RAD"
L2: "Inductor, Shielded Drum Core, Superflux, 1.1uH, 13A, 0.0032 ohm, SMD"
L3: library part 744822301, "Coupled inductor, 10mH, 1A, TH"
Logo1: library part TI_Logo, "Texas Instrument Corporate Signature"
Q1: "MOSFET, N-CH, 40V, 22A, SON 5x6mm"
Q2: library part IPP65R190CFD, "MOSFET N-CH 650V 10.6A TO220"
Q3: library part "MMBT2907A, Fairchild Semiconductor", "Transistor, PNP, 60V, 0.8A, SOT-23"
R1 R2: "RES, 100 k, 5%, 0.1 W, 0603"
R3: "RES, 0 ohm, 5%, 0.125W, 0805"
R4: "RES, 20.0, 1%, 0.25 W, 1206"
R5: "RES, 0, 5%, 0.063 W, 0402"
R6: "RES, 100 ohm, 1%, 0.063W, 0402"
R7: "RES, 49.9 k, 1%, 0.1 W, 0603"
R8: "RES, 221k ohm, 1%, 0.1W, 0603"
R9: "RES, 100, 5%, 0.25 W, 1206"
R10: "RES, 97.6 k, 1%, 0.1 W, 0603"
R11: "RES, 1.0, 5%, 0.25 W, 1206"
R12: "RES, 10 ohm, 5%, 0.1W, 0603"
R13: "RES, 100k ohm, 5%, 0.125W, 0805"
R14: "RES, 590, 1%, 0.1 W, 0603"
R15 R101: library part CSRN2010FKR400, "RES 0.47 OHM 1/2W 5% 2010 SMD"
R16 R17: "RES, 47.5 k, 1%, 0.1 W, 0603"
R18: "RES, 36.5 k, 1%, 0.1 W, 0603"
R19: "RES, 3.16 M, 1%, 0.1 W, 0603"
R20: "RES, 1.0 M, 5%, 0.1 W, 0603"
RT1: "Thermistor NTC, 10 ohm, 20%, Disc_11.5mmx6mm"
T1: "Transformer, 220 uH, TH"
U1: "Voltage Droop Monitor with Wake-Up Output, DBV0005A"
U2: "GREEN Rectifier Controller Device, D0008A"
U3: library part TPS71533DCK, "50 mA, 24 V, 3.2-mA Supply Current Low-Dropout Linear Regulator, DCK0005A"
U4: "Constant-Voltage Constant-Current Flyback Controller With PSR and Wake-Up Monitoring, D0007A"

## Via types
v1: diameter 28, hole 10, Top Layer to Bottom Layer, 41 vias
